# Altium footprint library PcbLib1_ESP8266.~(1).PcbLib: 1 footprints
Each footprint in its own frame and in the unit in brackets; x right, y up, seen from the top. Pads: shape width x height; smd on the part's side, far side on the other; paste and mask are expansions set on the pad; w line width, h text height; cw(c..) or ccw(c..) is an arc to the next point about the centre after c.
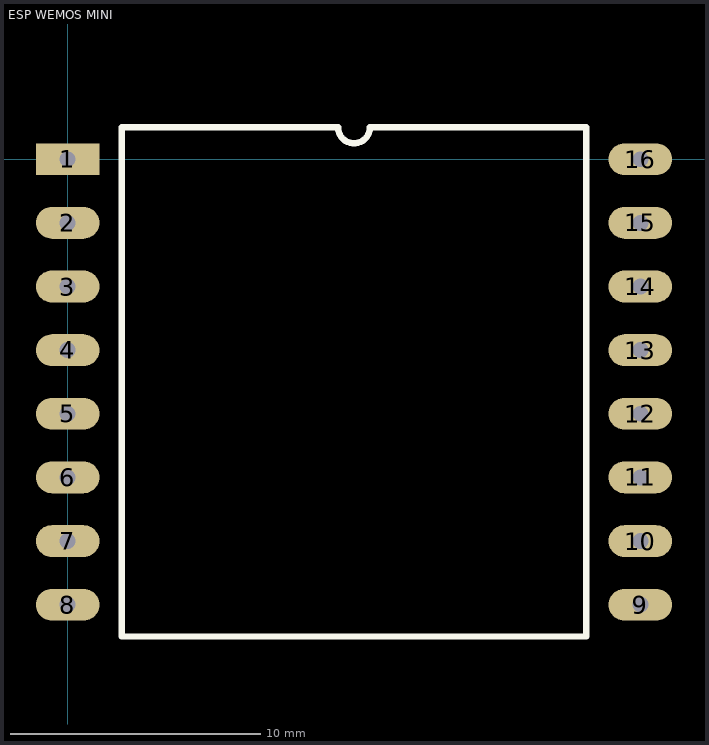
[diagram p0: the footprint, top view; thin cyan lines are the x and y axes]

## ESP WEMOS MINI [mil]
pads (16):
  rect 100x50 hole 25: 1(0,0)
  oval 100x50 hole 25: 2(0,-100) 3(0,-200) 4(0,-300) 5(0,-400) 6(0,-500) 7(0,-600) 8(0,-700) 9(900,-700) 10(900,-600) 11(900,-500) 12(900,-400) 13(900,-300) 14(900,-200) 15(900,-100) 16(900,0)
Top Overlay:
  lines w10: 85,-750 815,-750 815,50 475,50 cw(c450,50) 425,50 85,50 85,-750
